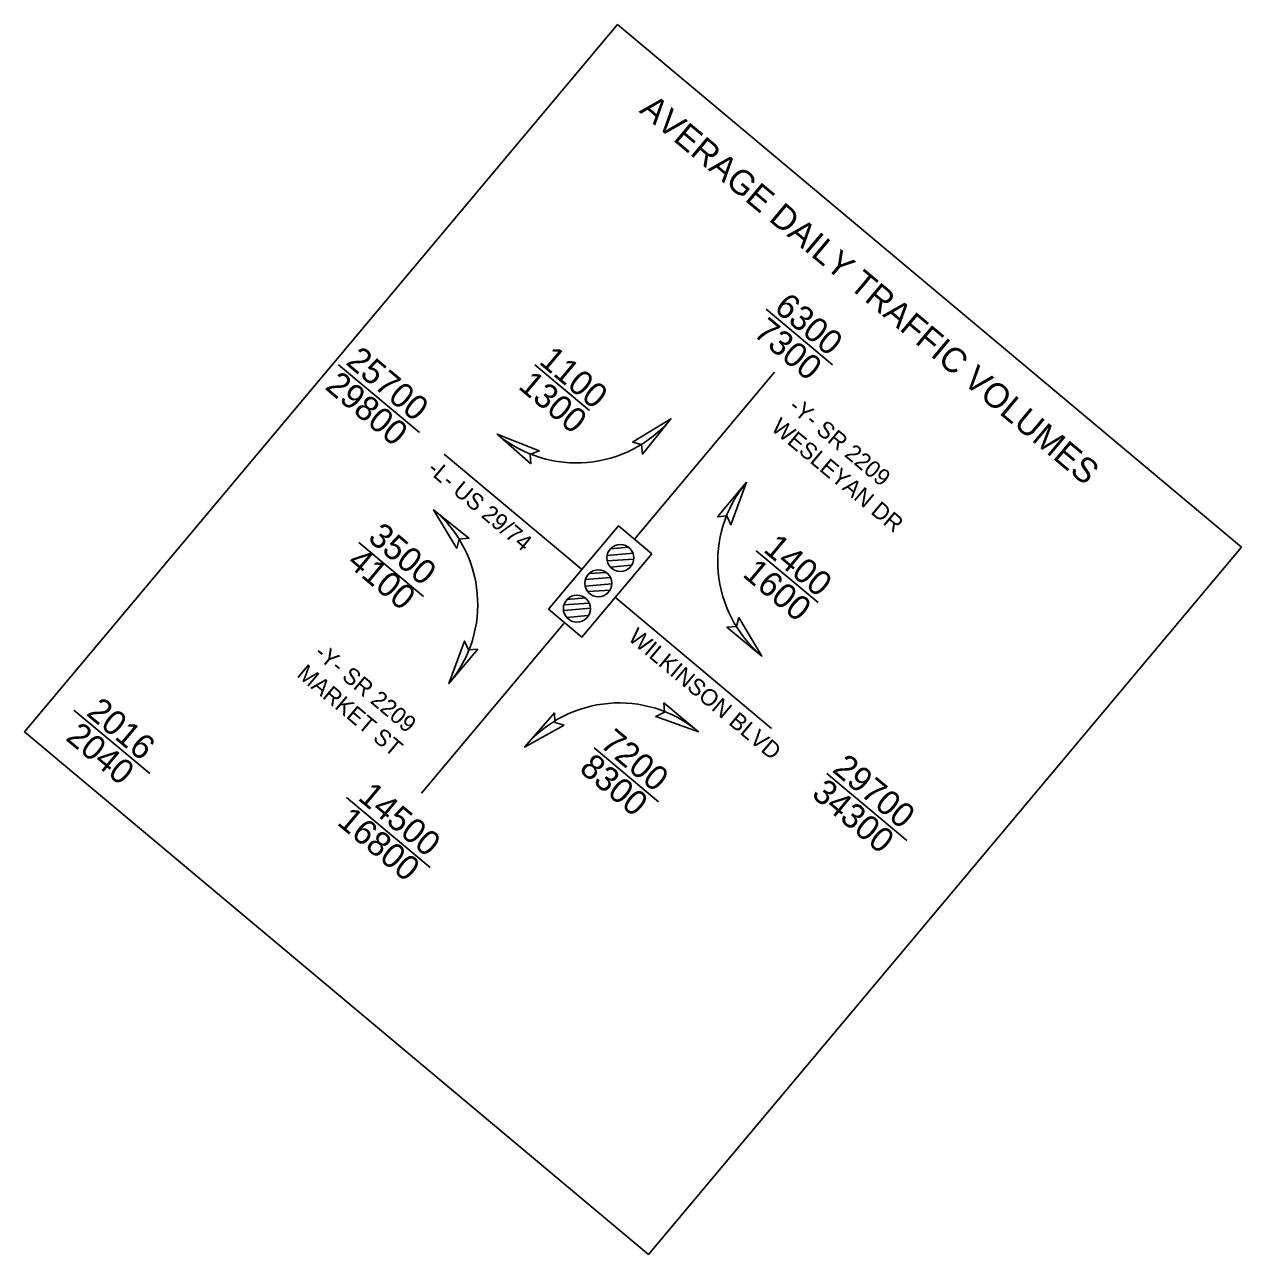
# Model space of a CAD drawing. Extents: x 1257249 to 1258387, y 800228 to 800957.
# Drawn here: x 1257249.5 to 1257495.9, y 800708 to 800957.2 of the extents above; entities that cross this region are included whole.
import ezdxf

# ---------------------------------------------------------------- set-up
doc = ezdxf.new("R2010")
doc.units = 0
for name, color, linetype in [('Exist PHM Traffic Signal CELL', 7, 'Continuous'), ('Pattern 1', 7, 'Continuous'), ('Prop DSN Text', 7, 'Continuous')]:
    doc.layers.add(name, color=color, linetype=linetype)

msp = doc.modelspace()

# ---------------------------------------------------------------- linework, layer by layer
at = {"layer": 'Exist PHM Traffic Signal CELL'}
for p, q in [((1257367.36, 800849.61), (1257372.73, 800850.08)), ((1257368.09, 800850.96), (1257371.82, 800851.33)), ((1257367.37, 800848.54), (1257372.83, 800848.93)), ((1257368.05, 800847.31), (1257372.28, 800847.69)), ((1257362.95, 800844.78), (1257368.11, 800845.19)), ((1257363.82, 800846.01), (1257367.22, 800846.18)), ((1257362.98, 800843.45), (1257368.35, 800843.92)), ((1257363.52, 800842.35), (1257368.07, 800842.61)), ((1257358.59, 800839.63), (1257363.84, 800839.96)), ((1257359.29, 800840.75), (1257363.08, 800841.09)), ((1257358.69, 800838.48), (1257364.06, 800838.96)), ((1257359.3, 800837.07), (1257363.48, 800837.48))]:
    msp.add_line(p, q, dxfattribs=at)
msp.add_lwpolyline([(1257376.45, 800849.98), (1257369.69, 800855.64), (1257355.56, 800838.78), (1257362.31, 800833.12)], close=True, dxfattribs=at)
for centre in [(1257370.09, 800849.15), (1257365.65, 800844), (1257361.3, 800838.88)]:
    msp.add_circle(centre, 2.74, dxfattribs=at)
at = {"layer": 'Pattern 1'}
for points in [[(1257372.53, 800872.6), (1257380.34, 800877.33), (1257374.56, 800870.19), (1257374.38, 800872.15)], [(1257351.96, 800868.18), (1257345.12, 800874.23), (1257353.66, 800870.83), (1257351.84, 800870.07)], [(1257389.79, 800857.49), (1257395.67, 800864.48), (1257392.49, 800855.86), (1257391.69, 800857.66)], [(1257337.01, 800851.09), (1257332.27, 800858.9), (1257339.42, 800853.12), (1257337.46, 800852.94)], [(1257394.08, 800837.1), (1257398.77, 800829.26), (1257391.66, 800835.09), (1257393.62, 800835.26)], [(1257341.25, 800830.67), (1257335.38, 800823.68), (1257338.56, 800832.3), (1257339.36, 800830.5)], [(1257378.89, 800819.76), (1257385.92, 800813.94), (1257377.28, 800817.05), (1257379.07, 800817.87)], [(1257358.69, 800815.26), (1257350.7, 800810.83), (1257356.76, 800817.75), (1257356.86, 800815.78)]]:
    msp.add_lwpolyline(points, close=True, dxfattribs=at)
for centre, start, end in [((1257361.18, 800893.39), 230.0343, 320.0343), ((1257414.83, 800848.43), 140.0343, 230.0343), ((1257316.22, 800839.74), 320.0343, 50.0343), ((1257369.87, 800794.78), 50.0343, 140.0343)]:
    msp.add_arc(centre, 25, start, end, dxfattribs=at)
at = {"layer": 'Prop DSN Text'}
for p, q in [((1257399.6, 800899.53), (1257413.06, 800888.26)), ((1257313.05, 800888.29), (1257329.44, 800874.55)), ((1257352.76, 800888.29), (1257363.84, 800879)), ((1257401.31, 800886.79), (1257372.95, 800852.94)), ((1257334.39, 800870.17), (1257362.13, 800846.92)), ((1257317.17, 800852.25), (1257330.22, 800841.31)), ((1257397.63, 800850.6), (1257410.14, 800840.12)), ((1257369.15, 800841.04), (1257400.72, 800814.59)), ((1257358.65, 800835.88), (1257329.82, 800801.48)), ((1257259.45, 800818.33), (1257274.8, 800805.47)), ((1257364.77, 800810.67), (1257377.83, 800799.73)), ((1257411.9, 800805.45), (1257428.1, 800791.87)), ((1257314.63, 800800.6), (1257331.55, 800786.43))]:
    msp.add_line(p, q, dxfattribs=at)
msp.add_lwpolyline([(1257249.45, 800813.93), (1257375.79, 800708.05), (1257495.86, 800851.31), (1257369.52, 800957.2)], close=True, dxfattribs=at)

# ---------------------------------------------------------------- texts
for s, height, p in [('AVERAGE DAILY TRAFFIC VOLUMES', 5, (1257373.76, 800939.56)), ('6300', 5, (1257401, 800899.41)), ('7300', 5, (1257396.79, 800894.38)), ('25700', 5, (1257314.29, 800888.53)), ('1100', 5, (1257353.41, 800888.65)), ('29800', 5, (1257310.08, 800883.51)), ('1300', 5, (1257349.2, 800883.63)), ('-Y- SR 2209', 3.375, (1257403.95, 800879.39)), ('WESLEYAN DR', 3.375, (1257400.42, 800875.19)), ('-L- US 29/74 ', 3.375, (1257330.78, 800866.74)), ('3500', 5, (1257318.72, 800852.86)), ('1400', 5, (1257398.84, 800850.58)), ('4100', 5, (1257314.51, 800847.84)), ('1600', 5, (1257394.63, 800845.55)), ('WILKINSON BLVD', 3.375, (1257371.45, 800832.66)), ('-Y- SR 2209', 3.375, (1257307.91, 800829.47)), ('MARKET ST', 3.375, (1257304.39, 800825.27)), ('2016', 5, (1257261.76, 800817.45)), ('2040', 5, (1257257.55, 800812.43)), ('7200', 5, (1257365.75, 800811.09)), ('8300', 5, (1257361.54, 800806.06)), ('29700', 5, (1257412.8, 800805.98)), ('14500', 5, (1257316.73, 800800.32)), ('34300', 5, (1257408.59, 800800.95)), ('16800', 5, (1257312.52, 800795.29))]:
    msp.add_text(s, height=height, rotation=320.0343, dxfattribs=at).set_placement(p)

doc.saveas('drawing.dxf')
